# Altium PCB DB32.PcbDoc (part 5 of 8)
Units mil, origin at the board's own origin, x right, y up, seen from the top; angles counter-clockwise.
Board outline 3236.22 x 4456.69 mil, 8 copper layers (Top Layer, MidLayer1, MidLayer2, GND-Layer5, MidLayer3, VCC, MidLayer4, Bottom Layer), stack 61.8 mil thick; 207 components, 474 nets, 1777 pads, 1474 vias.
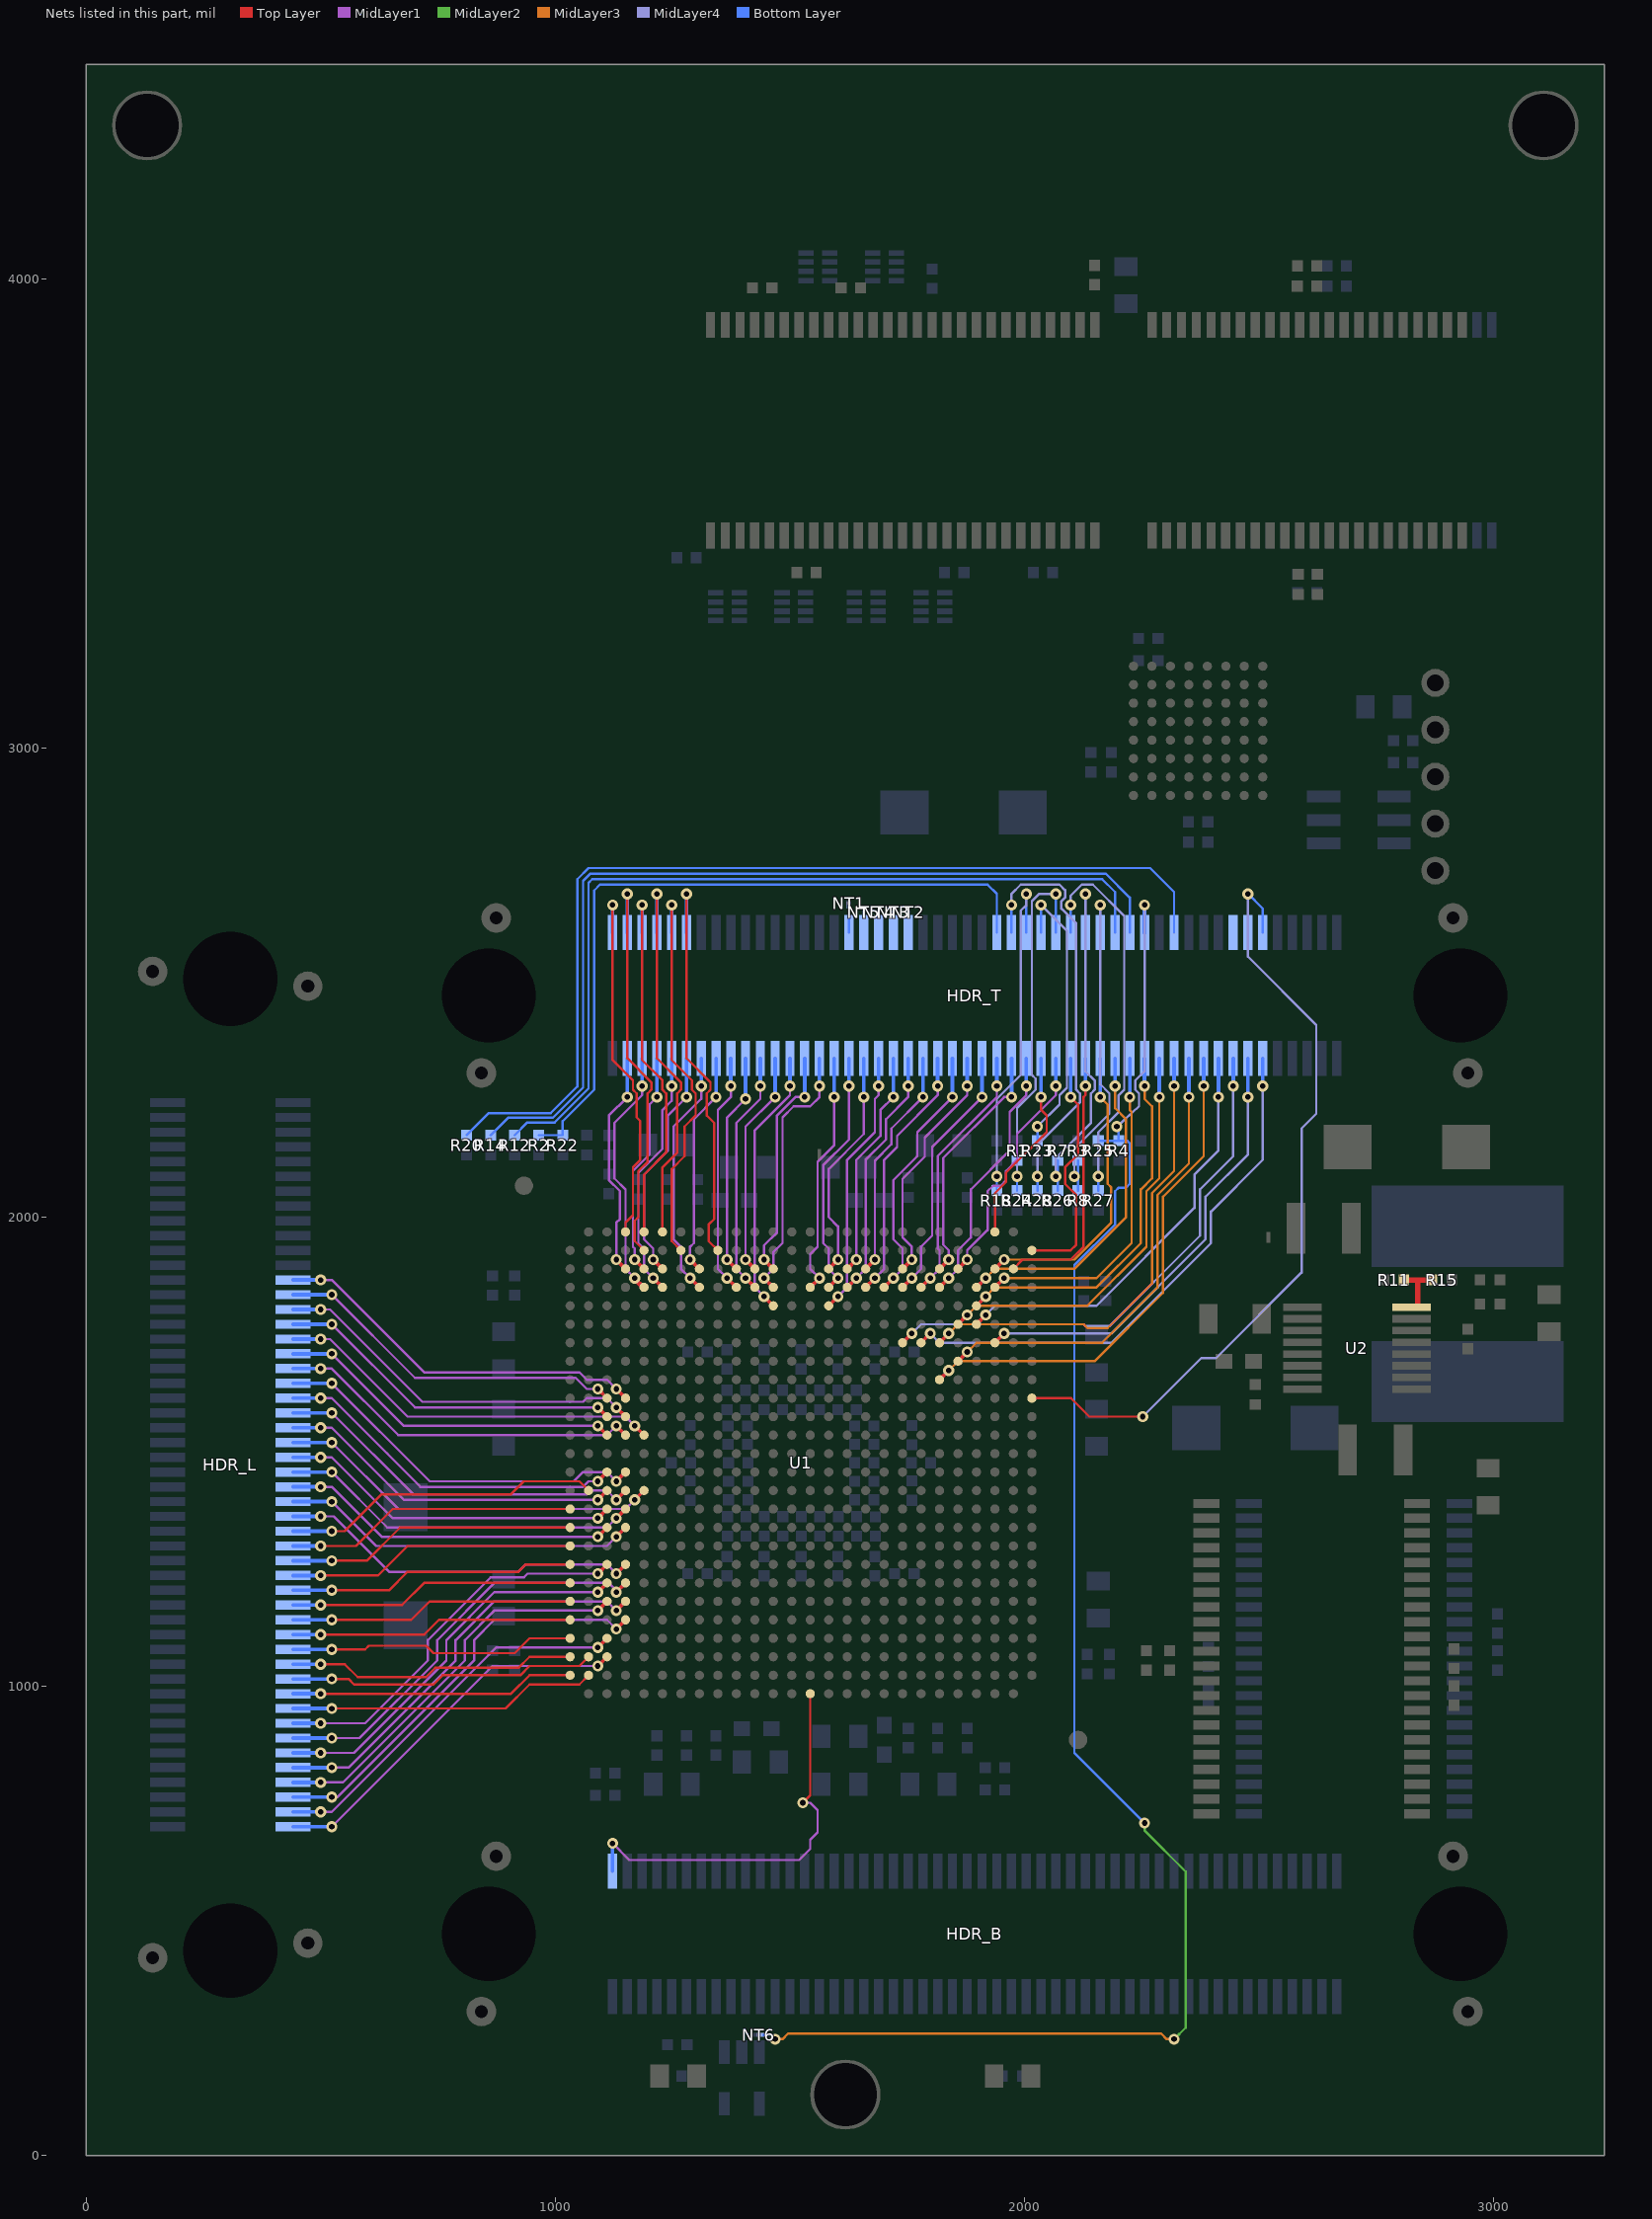
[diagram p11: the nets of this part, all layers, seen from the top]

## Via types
v1: diameter 23.62, hole 11.81, Top Layer to Bottom Layer, 839 vias
v2: diameter 23.62, hole 11.81, Top Layer to Bottom Layer, tented both sides, 499 vias
v3: diameter 27.56, hole 15.75, Top Layer to Bottom Layer, 135 vias
v4: diameter 23.62, hole 11.81, Top Layer to Bottom Layer, tented top, 1 vias

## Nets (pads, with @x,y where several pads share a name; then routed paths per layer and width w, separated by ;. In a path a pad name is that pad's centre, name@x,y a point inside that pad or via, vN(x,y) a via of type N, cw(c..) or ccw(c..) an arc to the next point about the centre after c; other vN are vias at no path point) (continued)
EXTEND_B12: HDR_L.26 U1.K4 | length 813
  Top Layer w7.87: v1(1129.92,1633.86) U1.K4@1149.61,1614.17
  MidLayer1 w5: v2(500,1866.14) 523.62,1866.14 720.47,1669.29 956.69,1669.29 968.5,1669.29 1051.18,1669.29 1066.93,1653.54 1110.23,1653.54 v1(1129.92,1633.86)
  Bottom Layer w7.87: HDR_L.26@440.94,1866.14 v2(500,1866.14)
EXTEND_B13: HDR_L.28 U1.K3 | length 760.6
  Top Layer w7.87: v1(1090.55,1633.86) U1.K3@1110.24,1614.17
  MidLayer1 w5: v2(523.62,1834.65) 700.79,1657.48 956.69,1657.48 968.5,1657.48 1043.31,1657.48 1066.93,1633.86 v1(1090.55,1633.86)
  Bottom Layer w7.87: HDR_L.28@440.94,1834.64 v2(523.62,1834.65)
EXTEND_B14: HDR_L.30 U1.L4 | length 809.8
  Top Layer w7.87: v1(1129.92,1594.49) U1.L4@1149.61,1574.8
  MidLayer1 w5: v2(500,1803.15) 519.68,1803.15 716.54,1606.3 956.69,1606.3 968.5,1606.3 1059.06,1606.3 1066.93,1614.17 1110.23,1614.17 v1(1129.92,1594.49)
  Bottom Layer w7.87: HDR_L.30@440.94,1803.15 v2(500,1803.15)
EXTEND_B15: HDR_L.32 U1.L3 | length 750.8
  Top Layer w7.87: v1(1090.55,1594.49) U1.L3@1110.24,1574.8
  MidLayer1 w5: v2(523.62,1771.66) 700.79,1594.49 956.69,1594.49 968.5,1594.49 v1(1090.55,1594.49)
  Bottom Layer w7.87: HDR_L.32@440.94,1771.65 v2(523.62,1771.66)
EXTEND_B16: HDR_L.34 U1.M5 | length 832.8
  Top Layer w7.87: v1(1169.29,1555.12) U1.M5@1188.98,1535.43
  MidLayer1 w5: v2(500,1740.16) 519.68,1740.16 685.04,1574.8 956.69,1574.8 968.5,1574.8 1149.61,1574.8 v1(1169.29,1555.12)
  Bottom Layer w7.87: HDR_L.34@440.94,1740.15 v2(500,1740.16)
EXTEND_B17: HDR_L.36 U1.M3 | length 741
  Top Layer w7.87: v1(1090.55,1555.12) U1.M3@1110.24,1535.43
  MidLayer1 w5: v2(523.62,1708.66) 677.17,1555.12 956.69,1555.12 968.51,1555.12 v1@1090.55,1555.12
  Bottom Layer w7.87: HDR_L.36@440.94,1708.66 v2(523.62,1708.66)
EXTEND_B18: HDR_L.38 U1.M4 | length 783.7
  Top Layer w7.87: v1(1129.92,1555.12) U1.M4@1149.61,1535.43
  MidLayer1 w5: v2(500,1677.17) 523.62,1677.17 665.36,1535.43 956.69,1535.43 968.5,1535.43 1110.23,1535.43 v1(1129.92,1555.12)
  Bottom Layer w7.87: HDR_L.38@440.94,1677.16 v2(500,1677.17)
EXTEND_B19: HDR_L.40 U1.P4 | length 819.6
  Top Layer w7.87: v1(1129.92,1437.01) U1.P4@1149.61,1456.69
  MidLayer1 w5: v2(523.62,1645.67) 732.29,1437.01 956.69,1437.01 968.5,1437.01 1039.37,1437.01 1059.06,1456.69 1110.23,1456.69 v1(1129.92,1437.01)
  Bottom Layer w7.87: HDR_L.40@440.94,1645.67 v2(523.62,1645.67)
EXTEND_B20: HDR_L.42 U1.P3 | length 760.6
  Top Layer w7.87: v1(1090.55,1437.01) U1.P3@1110.24,1456.69
  MidLayer1 w5: v2(500,1614.17) 523.62,1614.17 641.73,1496.06 712.6,1425.2 956.69,1425.2 968.5,1425.2 1059.06,1425.2 1070.87,1437.01 v1(1090.55,1437.01)
  Bottom Layer w7.87: HDR_L.42@440.94,1614.17 v2(500,1614.17)
EXTEND_B21: HDR_L.44 U1.R4 | length 800
  Top Layer w7.87: v1(1129.92,1397.64) U1.R4@1149.61,1417.32
  MidLayer1 w5: v2(523.62,1582.68) 696.85,1409.45 956.69,1409.45 968.5,1409.45 1066.93,1409.45 1074.8,1417.32 1110.23,1417.32 v1(1129.92,1397.64)
  Bottom Layer w7.87: HDR_L.44@440.94,1582.67 v2(523.62,1582.68)
EXTEND_B22: HDR_L.46 U1.R3 | length 741
  Top Layer w7.87: v1(1090.55,1397.64) U1.R3@1110.24,1417.32
  MidLayer1 w5: v2(500,1551.18) 523.62,1551.18 677.17,1397.64 956.69,1397.64 968.5,1397.64 v1(1090.55,1397.64)
  Bottom Layer w7.87: HDR_L.46@440.94,1551.18 v2(500,1551.18)
EXTEND_B23: HDR_L.48 U1.R5 | length 823
  Top Layer w7.87: v1(1169.29,1397.64) U1.R5@1188.98,1417.32
  MidLayer1 w5: v2(523.62,1519.68) 665.36,1377.95 956.69,1377.95 968.5,1377.95 1149.61,1377.95 v1(1169.29,1397.64)
  Bottom Layer w7.87: HDR_L.48@440.94,1519.68 v2(523.62,1519.68)
EXTEND_B24: HDR_L.50 U1.T3 | length 731.3
  Top Layer w7.87: v1(1090.55,1358.27) U1.T3@1110.24,1377.95
  MidLayer1 w5: v2(500,1488.19) 523.62,1488.19 653.54,1358.27 956.69,1358.27 968.5,1358.27 1062.99,1358.27 v1(1090.55,1358.27)
  Bottom Layer w7.87: HDR_L.50@440.94,1488.19 v2(500,1488.19)
EXTEND_B25: HDR_L.52 U1.T4 | length 773.9
  Top Layer w7.87: v1(1129.92,1358.27) U1.T4@1149.61,1377.95
  MidLayer1 w5: v2(523.62,1456.69) 641.73,1338.58 956.69,1338.58 968.5,1338.58 1110.24,1338.58 v1(1129.92,1358.27)
  Bottom Layer w7.87: HDR_L.52@440.94,1456.69 v2(523.62,1456.69)
EXTEND_B26: HDR_L.54 U1.U3 | length 721.5
  Top Layer w7.87: v1(1090.55,1318.9) U1.U3@1110.24,1338.58
  MidLayer1 w5: v2(500,1425.2) 523.62,1425.2 629.92,1318.9 956.69,1318.9 968.5,1318.9 v1(1090.55,1318.9)
  Bottom Layer w7.87: HDR_L.54@440.94,1425.19 v2(500,1425.2)
EXTEND_B27: HDR_L.56 U1.U4 | length 764.1
  Top Layer w7.87: v1(1129.92,1318.9) U1.U4@1149.61,1338.58
  MidLayer1 w5: v2(523.62,1393.7) 618.11,1299.21 956.69,1299.21 968.5,1299.21 1110.24,1299.21 v1(1129.92,1318.9)
  Bottom Layer w7.87: HDR_L.56@440.94,1393.7 v2(523.62,1393.7)
EXTEND_B28: HDR_L.58 U1.W4 | length 780.4
  Top Layer w7.87: v1(1129.92,1240.16) U1.W4@1149.61,1259.84
  MidLayer1 w5: v2(500,1362.21) 527.56,1362.21 645.67,1244.09 921.26,1244.09 937.01,1259.84 956.69,1259.84 968.5,1259.84 1110.23,1259.84 v1(1129.92,1240.16)
  Bottom Layer w7.87: HDR_L.58@440.94,1362.2 v2(500,1362.21)
EXTEND_B29: HDR_L.60 U1.R2 | length 682.1
  Top Layer w5: v2(523.62,1330.71) 551.18,1330.71 629.92,1409.45 905.51,1409.45 933.07,1437.01 956.69,1437.01 968.5,1437.01 1051.18,1437.01 U1.R2@1070.87,1417.32
  Bottom Layer w7.87: HDR_L.60@440.94,1330.71 v2(523.62,1330.71)
EXTEND_B30: HDR_L.62 U1.T1 | length 623.2
  Top Layer w5: v2(500,1299.21) 574.8,1299.21 653.54,1377.95 956.69,1377.95 968.5,1377.95 U1.T1@1031.5,1377.95
  Bottom Layer w7.87: HDR_L.62@440.94,1299.21 v2(500,1299.21)
EXTEND_B31: HDR_L.64 U1.U1 | length 619.9
  Top Layer w5: v2(523.62,1267.72) 598.43,1267.72 669.29,1338.58 956.69,1338.58 968.5,1338.58 U1.U1@1031.5,1338.58
  Bottom Layer w7.87: HDR_L.64@440.94,1267.71 v2(523.62,1267.72)
EXTEND_B32: HDR_L.66 U1.V1 | length 616.6
  Top Layer w5: v2(500,1236.22) 622.05,1236.22 685.04,1299.21 956.69,1299.21 968.5,1299.21 U1.V1@1031.5,1299.21
  Bottom Layer w7.87: HDR_L.66@440.94,1236.22 v2(500,1236.22)
EXTEND_B33: HDR_L.68 U1.W1 | length 613.4
  Top Layer w5: v2(523.62,1204.72) 645.67,1204.72 685.04,1244.09 921.26,1244.09 937.01,1259.84 956.69,1259.84 968.5,1259.84 U1.W1@1031.5,1259.84
  Bottom Layer w7.87: HDR_L.68@440.94,1204.72 v2(523.62,1204.72)
EXTEND_B34: HDR_L.70 U1.Y1 | length 610.1
  Top Layer w5: v2(500,1173.23) 673.23,1173.23 720.47,1220.47 956.69,1220.47 968.5,1220.47 U1.Y1@1031.5,1220.47
  Bottom Layer w7.87: HDR_L.70@440.94,1173.23 v2(500,1173.23)
EXTEND_B35: HDR_L.72 U1.AA1 | length 606.9
  Top Layer w5: v2(523.62,1141.73) 692.91,1141.73 732.28,1181.1 956.69,1181.1 968.5,1181.1 U1.AA1@1031.5,1181.1
  Bottom Layer w7.87: HDR_L.72@440.94,1141.73 v2(523.62,1141.73)
EXTEND_B36: HDR_L.74 U1.AB1 | length 603.6
  Top Layer w5: v2(500,1110.24) 720.47,1110.24 751.97,1141.73 956.69,1141.73 968.5,1141.73 U1.AB1@1031.5,1141.73
  Bottom Layer w7.87: HDR_L.74@440.94,1110.23 v2(500,1110.24)
EXTEND_B37: HDR_L.76 U1.AC1 | length 613.4
  Top Layer w5: v2(523.62,1078.74) 594.49,1078.74 602.36,1086.61 724.41,1086.61 740.16,1070.87 913.39,1070.87 944.88,1102.36 956.69,1102.36 968.5,1102.36 U1.AC1@1031.5,1102.36
  Bottom Layer w7.87: HDR_L.76@440.94,1078.74 v2(523.62,1078.74)
EXTEND_B38: HDR_L.78 U1.AD1 | length 619.9
  Top Layer w5: v2(500,1047.25) 551.18,1047.25 578.74,1019.68 724.41,1019.68 744.09,1039.37 921.26,1039.37 944.88,1062.99 956.69,1062.99 968.5,1062.99 U1.AD1@1031.5,1062.99
  Bottom Layer w7.87: HDR_L.78@440.94,1047.24 v2(500,1047.25)
EXTEND_B39: HDR_L.80 U1.AD2 | length 659.3
  Top Layer w5: v2(523.62,1015.75) 559.05,1015.75 570.87,1003.94 740.16,1003.94 759.84,1023.62 925.2,1023.62 944.88,1043.31 956.69,1043.31 968.5,1043.31 1051.18,1043.31 U1.AD2@1070.87,1062.99
  Bottom Layer w7.87: HDR_L.80@440.94,1015.74 v2(523.62,1015.75)
EXTEND_B40: HDR_L.82 U1.AE1 | length 606.9
  Top Layer w5: v2(500,984.25) 905.51,984.25 944.88,1023.62 956.69,1023.62 968.5,1023.62 U1.AE1@1031.5,1023.62
  Bottom Layer w7.87: HDR_L.82@440.94,984.25 v2(500,984.25)
EXTEND_B41: HDR_L.84 U1.AE2 | length 659.3
  Top Layer w5: v2(523.62,952.75) 893.7,952.75 944.88,1003.94 956.69,1003.94 968.5,1003.94 1051.18,1003.94 U1.AE2@1070.87,1023.62
  Bottom Layer w7.87: HDR_L.84@440.94,952.75 v2(523.62,952.75)
EXTEND_B42: HDR_L.86 U1.W3 | length 834.9
  Top Layer w7.87: v1(1090.55,1240.16) U1.W3@1110.24,1259.84
  MidLayer1 w5: v2(500,921.26) 594.49,921.26 728.35,1055.12 728.35,1098.43 862.2,1232.28 933.07,1232.28 940.94,1240.16 956.69,1240.16 968.5,1240.16 v1(1090.55,1240.16)
  Bottom Layer w7.87: HDR_L.86@440.94,921.26 v2(500,921.26)
EXTEND_B43: HDR_L.88 U1.Y4 | length 891.3
  Top Layer w7.87: v1(1129.92,1200.79) U1.Y4@1149.61,1220.47
  MidLayer1 w5: v2(523.62,889.76) 582.68,889.76 748.03,1055.12 748.03,1098.43 870.08,1220.47 956.69,1220.47 968.5,1220.47 1114.17,1220.47 1131.89,1202.76 v1@1133.86,1200.79
  Bottom Layer w7.87: HDR_L.88@440.94,889.76 v2(523.62,889.76)
EXTEND_B44: HDR_L.90 U1.Y3 | length 844.7
  Top Layer w7.87: v1(1090.55,1200.79) U1.Y3@1110.24,1220.47
  MidLayer1 w5: v2(500,858.27) 570.87,858.27 767.72,1055.12 767.72,1098.43 870.08,1200.79 956.69,1200.79 968.5,1200.79 v1(1090.55,1200.79)
  Bottom Layer w7.87: HDR_L.90@440.94,858.26 v2(500,858.27)
EXTEND_B45: HDR_L.92 U1.AA4 | length 924.9
  Top Layer w7.87: v1(1129.92,1161.42) U1.AA4@1149.61,1181.1 v1(1129.92,1161.42)
  MidLayer1 w5: v2(523.62,826.77) 559.05,826.77 787.4,1055.12 787.4,1098.43 870.08,1181.1 956.69,1181.1 968.5,1181.1 1110.23,1181.1 v1(1129.92,1161.42)
  Bottom Layer w7.87: HDR_L.92@440.94,826.77 v2(523.62,826.77)
EXTEND_B46: HDR_L.94 U1.AA3 | length 902
  Top Layer w7.87: v1(1090.55,1161.42) U1.AA3@1110.24,1181.1 v1(1090.55,1161.42)
  MidLayer1 w5: v2(500,795.28) 547.24,795.28 807.09,1055.12 807.09,1098.43 870.08,1161.42 956.69,1161.42 968.5,1161.42 v1(1090.55,1161.42) 1070.87,1161.41
  Bottom Layer w7.87: HDR_L.94@440.94,795.27 v2(500,795.28)
EXTEND_B47: HDR_L.96 U1.AB4 | length 974.1
  Top Layer w7.87: v1(1129.92,1122.05) U1.AB4@1149.61,1141.73 v1(1129.92,1122.05)
  MidLayer1 w5: v2(523.62,763.78) 535.43,763.78 826.77,1055.12 826.77,1098.43 870.08,1141.73 956.69,1141.73 968.5,1141.73 1110.23,1141.73 ; 1070.87,1141.73 1110.24,1141.73 ; v1(1129.92,1122.05) 1110.23,1141.73
  Bottom Layer w7.87: HDR_L.96@440.95,763.78 v2(523.62,763.78)
EXTEND_B48: HDR_L.98 U1.AC3 | length 822.6
  Top Layer w7.87: v1(1090.55,1082.68) U1.AC3@1110.24,1102.36
  MidLayer1 w5: v2(500,732.28) 523.62,732.28 874.02,1082.68 956.69,1082.68 968.5,1082.68 v1(1090.55,1082.68)
  Bottom Layer w7.87: HDR_L.98@440.94,732.28 v2(500,732.28)
EXTEND_B49: HDR_L.100 U1.AD3 | length 819.3
  Top Layer w7.87: v1(1090.55,1043.31) U1.AD3@1110.24,1062.99
  MidLayer1 w5: v2(523.62,700.79) 866.14,1043.31 956.69,1043.31 968.5,1043.3 v1(1090.55,1043.31)
  Bottom Layer w7.87: HDR_L.100@440.94,700.78 v2(523.62,700.79)
EXTEND_C0: HDR_T.89 U1.G20 | length 1220.9
  Top Layer w7.87: U1.G20@1779.53,1732.28 v1(1799.21,1751.97)
  MidLayer4 w5: v1(1799.21,1751.97) 1818.9,1732.28 2078.74,1732.28 2090.55,1732.28 2185.04,1732.28 2397.64,1944.88 2397.64,2011.81 2507.87,2122.05 v2(2507.87,2279.53)
  Bottom Layer w7.87: v2(2507.87,2279.53) HDR_T.89@2507.88,2338.58 v2(2507.87,2279.53)
EXTEND_C1: HDR_T.87 U1.G24 | length 963.5
  Top Layer w7.87: U1.G24@1937.01,1732.28 v1(1956.69,1751.97)
  MidLayer4 w5: v1(1956.69,1751.97) 2078.74,1751.97 2090.55,1751.97 2185.04,1751.97 2385.83,1952.76 2385.83,2043.31 2476.38,2133.86 v2(2476.38,2255.9)
  Bottom Layer w7.87: v2(2476.38,2255.9) HDR_T.87@2476.38,2338.58
EXTEND_C2: HDR_T.85 U1.G19 | length 1139
  Top Layer w7.87: U1.G19@1740.16,1732.28 v1(1759.84,1751.97)
  MidLayer4 w5: v1(1759.84,1751.97) 1779.53,1771.65 2078.74,1771.65 2090.55,1771.65 2125.98,1771.65 2129.92,1767.72 2181.1,1767.72 2374.02,1960.63 2374.02,2059.06 2444.88,2129.92 v2(2444.88,2279.53)
  Bottom Layer w7.87: v2(2444.88,2279.53) HDR_T.85@2444.88,2338.58
EXTEND_C3: HDR_T.83 U1.F23 | length 907.4
  Top Layer w7.87: U1.F23@1897.64,1771.65 v1(1917.33,1791.34)
  MidLayer4 w5: v1(1917.33,1791.34) 1937.01,1811.02 2078.74,1811.02 2090.55,1811.02 2153.54,1811.02 2362.2,2019.68 2362.2,2090.55 2413.38,2141.73 v2(2413.38,2255.9)
  Bottom Layer w7.87: v2(2413.38,2255.9) HDR_T.83@2413.39,2338.58
EXTEND_C4: HDR_T.81 U1.J21 | length 1088.9
  Top Layer w7.87: U1.J21@1818.9,1653.54 v1(1838.59,1673.23)
  MidLayer3 w5: v1(1838.59,1673.23) 1858.27,1692.91 2078.74,1692.91 2090.55,1692.91 2149.61,1692.91 2295.28,1838.58 2295.28,2043.31 2381.89,2129.92 v2(2381.89,2279.53)
  Bottom Layer w7.87: v2(2381.89,2279.53) HDR_T.81@2381.89,2338.58
EXTEND_C5: HDR_T.79 U1.H22 | length 1006.3
  Top Layer w7.87: U1.H22@1858.27,1692.91 v1(1877.96,1712.6)
  MidLayer3 w5: v1(1877.96,1712.6) 1897.64,1732.28 2078.74,1732.28 2090.55,1732.28 2165.35,1732.28 2283.46,1850.39 2283.46,2047.24 2350.39,2114.17 v2(2350.39,2255.9)
  Bottom Layer w7.87: v2(2350.39,2255.9) HDR_T.79@2350.4,2338.58
EXTEND_C6: HDR_T.77 U1.G21 | length 1011.3
  Top Layer w7.87: U1.G21@1818.9,1732.28 v1(1838.58,1751.97)
  MidLayer3 w5: v1(1838.58,1751.97) 1858.27,1771.65 2078.74,1771.65 2090.55,1771.65 2125.98,1771.65 2133.86,1763.78 2177.17,1763.78 2271.65,1858.27 2271.65,2051.18 2318.89,2098.42 v2(2318.89,2279.53)
  Bottom Layer w7.87: v2(2318.89,2279.53) HDR_T.77@2318.9,2338.58
EXTEND_C7: HDR_T.75 U1.F22 | length 883.1
  Top Layer w7.87: U1.F22@1858.27,1771.65 v1(1877.96,1791.34)
  MidLayer3 w5: v1(1877.96,1791.34) 1897.64,1811.02 2078.74,1811.02 2090.55,1811.02 2133.86,1811.02 2259.84,1937.01 2259.84,2055.12 2287.4,2082.68 v2(2287.4,2255.9)
  Bottom Layer w7.87: v2(2287.4,2255.9) HDR_T.75@2287.4,2338.58
EXTEND_C8: HDR_T.73 U1.E23 | length 815.8
  Top Layer w7.87: U1.E23@1897.64,1811.02 v1(1917.32,1830.71)
  MidLayer3 w5: v1(1917.32,1830.71) 1937.01,1850.39 2078.74,1850.39 2090.55,1850.39 2153.54,1850.39 2248.03,1944.88 2248.03,2059.06 2271.65,2082.68 2271.65,2236.21 2255.9,2251.97 v2(2255.9,2279.53)
  Bottom Layer w7.87: v2(2255.9,2279.53) HDR_T.73@2255.91,2338.58
EXTEND_C9: HDR_T.71 U1.D24 | length 725.8
  Top Layer w7.87: U1.D24@1937.01,1850.39 v1(1956.7,1870.08)
  MidLayer3 w5: v1(1956.7,1870.08) 2078.74,1870.08 2090.55,1870.08 2153.54,1870.08 2228.35,1944.88 2228.35,2224.41 2224.41,2228.35 v2(2224.41,2255.9)
  Bottom Layer w7.87: v2(2224.41,2255.9) HDR_T.71@2224.41,2338.58
EXTEND_C10: HDR_T.69 U1.D23 | length 729.2
  Top Layer w7.87: U1.D23@1897.64,1850.39 v1(1917.33,1870.08)
  MidLayer3 w5: v1(1917.33,1870.08) 1937.01,1889.76 2078.74,1889.76 2090.55,1889.76 2106.3,1889.76 2216.54,2000 2216.54,2208.66 2192.91,2232.29 v2(2192.91,2279.53)
  Bottom Layer w7.87: v2(2192.91,2279.53) HDR_T.69@2192.91,2338.58
EXTEND_C11: HDR_T.67 U1.C24 | length 649
  Top Layer w7.87: U1.C24@1937.01,1889.76 v1(1956.69,1909.45)
  MidLayer3 w5: v1(1956.69,1909.45) 2078.74,1909.45 2090.55,1909.45 2106.3,1909.45 2185.04,1988.19 2185.04,2062.99 2177.16,2070.87 2177.16,2240.16 v2(2161.42,2255.9)
  Bottom Layer w7.87: v2(2161.42,2255.9) HDR_T.67@2161.42,2338.58
EXTEND_C12: HDR_T.65 U1.C25 | length 572.4
  Top Layer w5: U1.C25@1976.38,1889.76 1996.06,1909.45 2078.74,1909.45 2090.55,1909.45 2098.43,1909.45 2125.98,1937.01 2125.98,2255.91 2129.92,2259.84 v2(2129.92,2279.53)
  Bottom Layer w7.87: v2(2129.92,2279.53) HDR_T.65@2129.92,2338.58
EXTEND_C13: HDR_T.63 U1.B26 | length 524.7
  Top Layer w5: U1.B26@2015.75,1929.13 2078.74,1929.13 2090.55,1929.13 2098.43,1929.13 2110.24,1940.94 2110.24,2047.24 2086.61,2070.87 2086.61,2106.3 2114.17,2133.86 2114.17,2240.16 v2(2098.42,2255.9)
  Bottom Layer w7.87: v2(2098.42,2255.9) HDR_T.63@2098.43,2338.58
EXTEND_C14: HDR_T.61 U1.C22 | length 544.5
  Top Layer w7.87: U1.C22@1858.27,1889.76 v1(1877.95,1909.45)
  MidLayer1 w5: v1(1877.95,1909.45) 1877.95,1929.13 1921.26,1972.44 1921.26,2031.5 1921.26,2043.31 1921.26,2055.12 1933.07,2066.93 1948.82,2066.93 1960.63,2078.74 1960.63,2098.43 1984.25,2122.05 1984.25,2177.17 2066.93,2259.84 v2(2066.93,2279.53)
  Bottom Layer w7.87: v2(2066.93,2279.53) HDR_T.61@2066.93,2338.58
EXTEND_C15: HDR_T.59 U1.A24 | length 420.6
  Top Layer w5: U1.A24@1937.01,1968.5 1937.01,2031.49 1937.01,2043.31 1937.01,2051.18 1960.63,2074.8 1960.63,2094.49 2047.24,2181.1 2047.24,2216.54 2035.43,2228.35 v2(2035.43,2255.9)
  Bottom Layer w7.87: v2(2035.43,2255.9) HDR_T.59@2035.43,2338.58
EXTEND_C16: HDR_T.57 U1.D21 | length 564.8
  Top Layer w7.87: U1.D21@1818.9,1850.39 v1(1838.59,1870.08)
  MidLayer1 w5: v1(1838.59,1870.08) 1858.27,1889.76 1858.27,1929.13 1885.83,1956.69 1885.83,2031.5 1885.83,2043.31 1885.83,2059.06 1968.5,2141.73 1968.5,2224.41 2003.94,2259.84 v2(2003.93,2279.53)
  Bottom Layer w7.87: v2(2003.93,2279.53) HDR_T.57@2003.94,2338.58
EXTEND_C17: HDR_T.55 U1.C21 | length 531.4
  Top Layer w7.87: U1.C21@1818.9,1889.76 v1(1838.58,1909.45)
  MidLayer1 w5: v1(1838.58,1909.45) 1838.58,1929.13 1826.77,1940.95 1826.77,2031.5 1826.77,2043.31 1826.77,2125.98 1956.69,2255.9 v2(1972.44,2255.9)
  Bottom Layer w7.87: v2(1972.44,2255.9) HDR_T.55@1972.44,2338.58
EXTEND_C18: HDR_T.53 U1.D20 | length 558.3
  Top Layer w7.87: U1.D20@1779.53,1850.39 v1(1799.21,1870.08)
  MidLayer1 w5: v1(1799.21,1870.08) 1818.9,1889.76 1818.9,1929.13 1814.96,1933.07 1814.96,2031.5 1814.96,2043.31 1814.96,2129.92 1940.94,2255.9 v2(1940.94,2279.53)
  Bottom Layer w7.87: v2(1940.94,2279.53) HDR_T.53@1940.95,2338.58
EXTEND_C19: HDR_T.51 U1.D19 | length 558.3
  Top Layer w7.87: U1.D19@1740.16,1850.39 v1(1759.84,1870.08)
  MidLayer1 w5: v1(1759.84,1870.08) 1779.53,1889.76 1779.53,1937.01 1803.15,1960.63 1803.15,2031.5 1803.15,2043.31 1803.15,2149.61 v2(1909.45,2255.9)
  Bottom Layer w7.87: v2(1909.45,2255.9) HDR_T.51@1909.45,2338.58
EXTEND_C20: HDR_T.49 U1.C19 | length 522.2
  Top Layer w7.87: U1.C19@1740.16,1889.76 v1(1759.84,1909.45)
  MidLayer1 w5: v1(1759.84,1909.45) 1759.84,1937.01 1740.16,1956.7 1740.16,2031.5 1740.16,2043.31 1740.16,2081.69 1787.4,2128.94 1787.4,2169.29 1877.95,2259.84 v2(1877.95,2279.53)
  Bottom Layer w7.87: v2(1877.95,2279.53) HDR_T.49@1877.95,2338.58
EXTEND_C21: HDR_T.47 U1.D18 | length 564.8
  Top Layer w7.87: U1.D18@1700.79,1850.39 v1(1720.47,1870.08)
  MidLayer1 w5: v1(1720.47,1870.08) 1740.16,1889.76 1740.16,1933.07 1720.47,1952.76 1720.47,2031.5 1720.47,2043.31 1720.47,2078.74 1771.65,2129.92 1771.65,2181.1 v2(1846.46,2255.9)
  Bottom Layer w7.87: v2(1846.46,2255.9) HDR_T.47@1846.46,2338.58
EXTEND_C22: HDR_T.45 U1.D17 | length 551.8
  Top Layer w7.87: U1.D17@1661.42,1850.39 v1(1681.1,1870.08)
  MidLayer1 w5: v1(1681.1,1870.08) 1700.79,1889.77 1700.79,2031.5 1700.79,2043.31 1700.79,2122.05 1728.35,2149.61 1728.35,2173.23 1814.96,2259.84 v2(1814.96,2279.53)
  Bottom Layer w7.87: v2(1814.96,2279.53) HDR_T.45@1814.96,2338.58
EXTEND_C23: HDR_T.43 U1.C17 | length 499.4
  Top Layer w7.87: U1.C17@1661.42,1889.76 v1(1681.1,1909.45)
  MidLayer1 w5: v1(1681.1,1909.45) 1681.1,2031.5 1681.1,2043.31 1681.1,2120.08 1716.54,2155.51 1716.54,2188.98 v2(1783.46,2255.9)
  Bottom Layer w7.87: v2(1783.46,2255.9) HDR_T.43@1783.47,2338.58
EXTEND_C24: HDR_T.41 U1.D16 | length 542
  Top Layer w7.87: U1.D16@1622.05,1850.39 v1(1641.73,1870.08)
  MidLayer1 w5: v1(1641.73,1870.08) 1661.42,1889.77 1661.42,2031.5 1661.42,2043.31 1661.42,2122.05 1704.72,2165.35 1704.72,2208.66 1751.97,2255.9 v2(1751.97,2279.53)
  Bottom Layer w7.87: v2(1751.97,2279.53) HDR_T.41@1751.97,2338.58
EXTEND_C25: HDR_T.39 U1.C16 | length 489.6
  Top Layer w7.87: U1.C16@1622.05,1889.76 v1(1641.73,1909.45)
  MidLayer1 w5: v1(1641.73,1909.45) 1641.73,2031.5 1641.73,2043.31 1641.73,2122.05 1692.91,2173.23 1692.91,2228.35 v2(1720.47,2255.9)
  Bottom Layer w7.87: v2(1720.47,2255.9) HDR_T.39@1720.47,2338.58
EXTEND_C26: HDR_T.37 U1.E15 | length 571.6
  Top Layer w7.87: U1.E15@1582.68,1811.02 v1(1602.36,1830.71)
  MidLayer1 w5: v1(1602.36,1830.71) 1622.05,1850.39 1622.05,2031.5 1622.05,2043.31 1622.05,2122.05 1681.1,2181.1 1681.1,2251.97 1688.98,2259.84 v2(1688.97,2279.53)
  Bottom Layer w7.87: v2(1688.97,2279.53) HDR_T.37@1688.98,2338.58
EXTEND_C27: HDR_T.35 U1.C15 | length 496.1
  Top Layer w7.87: U1.C15@1582.68,1889.76 v1(1602.36,1909.45)
  MidLayer1 w5: v1(1602.36,1909.45) 1602.36,1980.32 1582.68,2000 1582.68,2031.5 1582.68,2043.31 1582.68,2102.36 1657.48,2177.16 v2(1657.48,2255.9)
  Bottom Layer w7.87: v2(1657.48,2255.9) HDR_T.35@1657.48,2338.58
EXTEND_C28: HDR_T.33 U1.D15 | length 532.2
  Top Layer w7.87: U1.D15@1582.68,1850.39 v1(1602.36,1870.08)
  MidLayer1 w5: v1(1602.36,1870.08) 1582.68,1889.77 1582.68,1933.07 1570.87,1944.88 1570.87,2031.5 1570.87,2043.31 1570.87,2110.24 1625.98,2165.35 v2(1625.98,2279.53)
  Bottom Layer w7.87: v2(1625.98,2279.53) HDR_T.33@1625.99,2338.58
EXTEND_C29: HDR_T.31 U1.D14 | length 525.7
  Top Layer w7.87: U1.D14@1543.31,1850.39 v1(1562.99,1870.08)
  MidLayer1 w5: v1(1562.99,1870.08) 1543.31,1889.77 1543.31,1921.26 1559.06,1937.01 1559.06,2031.5 1559.06,2043.31 1559.06,2118.11 1562.99,2122.05 1594.49,2153.54 v2(1594.49,2255.9)
  Bottom Layer w7.87: v2(1594.49,2255.9) HDR_T.31@1594.49,2338.58
EXTEND_C30: HDR_T.29 U1.D12 | length 566
  Top Layer w7.87: v1(1444.88,1870.08) U1.D12@1464.57,1850.39
  MidLayer1 w5: v1(1444.88,1870.08) 1464.57,1889.77 1464.57,1925.2 1484.25,1944.88 1484.25,2031.5 1484.25,2043.31 1484.25,2212.6 1507.87,2236.22 1543.31,2236.22 1562.99,2255.9 v2(1562.99,2279.53)
  Bottom Layer w7.87: v2(1562.99,2279.53) HDR_T.29@1562.99,2338.58
EXTEND_C31: HDR_T.27 U1.C12 | length 504.4
  Top Layer w7.87: v1(1444.88,1909.45) U1.C12@1464.57,1889.76
  MidLayer1 w5: v1(1444.88,1909.45) 1444.88,1939.96 1472.44,1967.52 1472.44,2031.5 1472.44,2043.31 1472.44,2216.54 1511.81,2255.9 v2(1531.5,2255.9)
  Bottom Layer w7.87: v2(1531.5,2255.9) HDR_T.27@1531.5,2338.58
EXTEND_C32: HDR_T.25 U1.E12 | length 574.9
  Top Layer w7.87: v1(1444.88,1830.71) U1.E12@1464.57,1811.02
  MidLayer1 w5: v1(1444.88,1830.71) 1425.2,1850.39 1425.2,2031.5 1425.2,2043.31 1425.2,2185.04 1500,2259.84 v2(1500,2279.53)
  Bottom Layer w7.87: v2(1500,2279.53) HDR_T.25@1500,2338.58
EXTEND_C33: HDR_T.23 U1.C11 | length 483.1
  Top Layer w7.87: v1(1405.51,1909.45) U1.C11@1425.2,1889.76
  MidLayer1 w5: v1(1405.51,1909.45) 1405.51,2031.5 1405.51,2043.31 1405.51,2192.91 v2(1468.5,2255.9)
  Bottom Layer w7.87: v2(1468.5,2255.9) HDR_T.23@1468.5,2338.58
EXTEND_C34: HDR_T.21 U1.D11 | length 525.7
  Top Layer w7.87: v1(1405.51,1870.08) U1.D11@1425.2,1850.39
  MidLayer1 w5: v1(1405.51,1870.08) 1385.83,1889.76 1385.83,2031.5 1385.83,2043.31 1385.83,2200.79 1437.01,2251.97 v2(1437.01,2279.53)
  Bottom Layer w7.87: v2(1437.01,2279.53) HDR_T.21@1437.01,2338.58
EXTEND_C35: HDR_T.19 U1.C10 | length 469.3
  Top Layer w7.87: v1(1366.14,1909.45) U1.C10@1385.83,1889.76
  MidLayer1 w5: v1(1366.14,1909.45) 1366.14,2031.5 1366.14,2043.31 1366.14,2212.6 v2(1405.51,2251.97)
  Bottom Layer w7.87: v2@1405.51,2255.9 HDR_T.19@1405.51,2338.58
EXTEND_C36: HDR_T.17 U1.D10 | length 515.9
  Top Layer w7.87: v1(1366.14,1870.08) U1.D10@1385.83,1850.39
  MidLayer1 w5: v1(1366.14,1870.08) 1346.46,1889.76 1346.46,2031.5 1346.46,2043.31 1346.46,2228.35 1374.02,2255.91 v2(1374.02,2279.53)
  Bottom Layer w7.87: v2(1374.02,2279.53) HDR_T.17@1374.02,2338.58
EXTEND_C37: HDR_T.15 U1.C8 | length 479.8
  Top Layer w7.87: v1(1287.4,1909.45) U1.C8@1307.09,1889.76
  MidLayer1 w5: v1(1287.4,1909.45) 1287.4,1937.01 1295.28,1944.89 1295.28,2031.5 1295.28,2043.31 1295.28,2208.66 v2(1342.52,2255.9)
  Bottom Layer w7.87: v2(1342.52,2255.9) HDR_T.15@1342.52,2338.58
EXTEND_C38: HDR_T.13 U1.D8 | length 535.5
  Top Layer w7.87: v1(1287.4,1870.08) U1.D8@1307.09,1850.39
  MidLayer1 w5: v1(1287.4,1870.08) 1267.72,1889.76 1267.72,1937.01 1251.97,1952.76 1251.97,2031.5 1251.97,2043.31 1251.97,2192.91 1311.02,2251.97 v2(1311.02,2279.53)
  Bottom Layer w7.87: v2(1311.02,2279.53) HDR_T.13@1311.02,2338.58
EXTEND_C39: HDR_T.11 U1.C6 | length 502.6
  Top Layer w7.87: v1(1208.66,1909.45) U1.C6@1228.35,1889.76
  MidLayer1 w5: v1(1208.66,1909.45) 1208.66,1933.07 1188.98,1952.76 1188.98,2031.5 1188.98,2043.31 1188.98,2090.55 1240.16,2141.73 1240.16,2216.53 v2(1279.53,2255.9)
  Bottom Layer w7.87: v2(1279.53,2255.9) HDR_T.11@1279.53,2338.58
EXTEND_C40: HDR_T.12 U1.B9 | length 886.5
  Top Layer w5: v2(1279.53,2688.98) 1279.53,2338.58 1330.71,2287.4 1330.71,2271.65 1322.83,2263.78 1322.83,2216.54 1338.58,2200.79 1338.58,2043.31 1338.58,2031.5 1338.58,1996.06 1326.77,1984.25 1326.77,1948.82 U1.B9@1346.46,1929.13
  Bottom Layer w7.87: HDR_T.12@1279.53,2606.3 v2(1279.53,2688.98)
EXTEND_C41: HDR_T.9 U1.D6 | length 538.7
  Top Layer w7.87: v1(1208.66,1870.08) U1.D6@1228.35,1850.39
  MidLayer1 w5: v1(1208.66,1870.08) 1188.98,1889.76 1188.98,1933.07 1177.17,1944.88 1177.17,2031.5 1177.17,2043.31 1177.17,2094.49 1228.35,2145.67 1228.35,2228.35 1248.03,2248.03 v2(1248.03,2279.53)
  Bottom Layer w7.87: v2(1248.03,2279.53) HDR_T.9@1248.03,2338.58
EXTEND_C42: HDR_T.10 U1.B7 | length 845.8
  Top Layer w5: v2(1248.03,2665.35) 1248.03,2334.65 1291.34,2291.34 1291.34,2271.65 1299.21,2263.78 1299.21,2216.54 1275.59,2192.91 1275.59,2129.92 1248.03,2102.36 1248.03,2043.31 1248.03,2031.49 1248.03,1948.82 U1.B7@1267.72,1929.13
  Bottom Layer w7.87: HDR_T.10@1248.03,2606.3 v2(1248.03,2665.35)
EXTEND_C43: HDR_T.7 U1.C5 | length 479.8
  Top Layer w7.87: v1(1169.29,1909.45) U1.C5@1188.98,1889.76
  MidLayer1 w5: v1(1169.29,1909.45) 1169.29,1933.07 1165.35,1937.01 1165.35,2031.5 1165.35,2043.31 1165.35,2098.43 1200.79,2133.86 1200.79,2240.16 v2(1216.54,2255.9)
  Bottom Layer w7.87: v2(1216.54,2255.9) HDR_T.7@1216.54,2338.58
EXTEND_C44: HDR_T.8 U1.A6 | length 840.7
  Top Layer w5: v2(1216.54,2688.98) 1216.54,2338.58 1267.72,2287.4 1267.72,2271.65 1259.84,2263.78 1259.84,2137.8 1228.35,2106.3 1228.35,2043.31 1228.35,2031.5 U1.A6@1228.35,1968.5
  Bottom Layer w7.87: HDR_T.8@1216.54,2606.3 v2(1216.54,2688.98)
EXTEND_C45: HDR_T.5 U1.D5 | length 566.6
  Top Layer w7.87: v1@1169.28,1866.15 U1.D5@1188.97,1846.46 ; v1(1169.29,1870.08) U1.D5@1188.98,1850.39
  MidLayer1 w5: v1(1169.29,1870.08) 1149.61,1889.76 1149.61,2031.5 1149.61,2043.31 1149.61,2059.06 1125.98,2082.68 1125.98,2200.79 1185.04,2259.84 v2(1185.04,2279.53)
  Bottom Layer w7.87: v2(1185.04,2279.53) HDR_T.5@1185.04,2338.58
EXTEND_C46: HDR_T.6 U1.A5 | length 855.7
  Top Layer w5: v2(1185.04,2665.35) 1185.04,2334.65 1228.35,2291.34 1228.35,2271.65 1236.22,2263.78 1236.22,2137.8 1188.98,2090.55 1188.98,2043.31 1188.98,2031.5 U1.A5@1188.98,1968.5
  Bottom Layer w7.87: HDR_T.6@1185.04,2606.3 v2(1185.04,2665.35) HDR_T.6@1185.04,2606.3
EXTEND_C47: HDR_T.3 U1.C4 | length 486.3
  Top Layer w7.87: v1(1129.92,1909.45) U1.C4@1149.61,1889.76
  MidLayer1 w5: v1(1129.92,1909.45) 1129.92,1988.19 1137.8,1996.06 1137.8,2031.5 1137.8,2043.31 1137.8,2055.12 1114.17,2078.74 1114.17,2216.53 v2(1153.54,2255.9)
  Bottom Layer w7.87: v2(1153.54,2255.9) HDR_T.3@1153.54,2338.58
EXTEND_C48: HDR_T.4 U1.B5 | length 945.6
  Top Layer w5: v2(1153.54,2688.98) 1153.54,2338.58 1204.72,2287.4 1204.72,2271.65 1196.85,2263.78 1196.85,2118.11 1177.17,2098.43 1177.17,2043.31 1177.17,2031.49 1177.17,2000 1169.29,1992.13 1169.29,1948.82 U1.B5@1188.98,1929.13
  Bottom Layer w7.87: 1153.54,2665.35 HDR_T.4@1153.54,2606.3 v2(1153.54,2688.98)
EXTEND_C49: HDR_T.2 U1.A4 | length 793.4
  Top Layer w5: v2(1122.05,2665.35) 1122.05,2334.65 1165.35,2291.34 1165.35,2271.65 1173.23,2263.78 1173.23,2212.6 1181.1,2204.72 1181.1,2122.05 1165.35,2106.3 1165.35,2043.31 1165.35,2031.5 1165.35,2003.94 1149.61,1988.19 U1.A4@1149.61,1968.5
  Bottom Layer w7.87: HDR_T.2@1122.05,2606.3 v2(1122.05,2665.35)
FB: R11.2 R15.1 U2.8 | length 120.2
  Top Layer w7.87: U2.8@2842.51,1807.09 U2.8@2842.51,1808.25
  Top Layer w11.81: R11.2@2808.58,1866.14 2838.58,1866.14 ; U2.8@2838.58,1807.09 2838.58,1808.25 2838.58,1866.14 ; R15.1@2868.58,1866.14 2838.58,1866.14
FPGA_CCLK: HDR_T.66 R7.1 R26.1 | length 791.4
  MidLayer4 w5: v2(2066.93,2086.61) 2066.93,2125.98 2141.73,2200.79 2141.73,2263.78 2149.61,2271.65 2149.61,2291.34 2129.92,2311.02 v2(2129.92,2688.98)
  Bottom Layer w5: R26.1@2070.86,2056.61 2070.86,2086.61 R7.1@2070.86,2120.55 ; HDR_T.66@2129.92,2606.3 v2(2129.92,2688.98)
FPGA_CLK: HDR_B.2 U1.AF14 | length 870.8
  Top Layer w5: v1(1527.56,751.97) 1543.31,767.72 U1.AF14@1543.31,984.25
  MidLayer1 w5: v2(1122.05,665.35) 1157.48,629.92 1519.69,629.92 1543.31,653.54 1543.31,673.23 1559.06,688.98 1559.06,736.22 1543.31,751.97 v1(1527.56,751.97)
  Bottom Layer w7.87: HDR_B.2@1122.05,606.3 v2(1122.05,665.35)
FPGA_CLK1: HDR_T.90 U1.K26 | length 1694.4
  Top Layer w5: U1.K26@2015.75,1614.17 2099.12,1614.17 2138.5,1574.79 v1(2251.96,1574.79)
  MidLayer4 w5: v1(2251.96,1574.79) 2376.85,1699.68 2408.1,1699.68 ; 2408.22,1699.56 2590.55,1881.89 2590.55,2188.98 2622.05,2220.47 2622.05,2409.45 2476.38,2555.12 v2(2476.38,2688.98)
  Bottom Layer w5: v2(2476.38,2688.98) 2507.87,2657.48 HDR_T.90@2507.88,2606.3
FPGA_DIN: HDR_T.64 R27.1 | length 842.3
  MidLayer4 w5: v2(2098.43,2665.35) 2098.43,2685.04 2122.05,2708.66 2145.67,2708.66 2212.6,2641.73 2212.6,2271.65 2200.79,2259.84 2200.79,2224.41 2157.48,2181.1 v2(2157.48,2086.61)
  Bottom Layer w5: HDR_T.64@2098.43,2606.3 v2(2098.43,2665.35) v2@2098.43,2669.29 ; R27.1@2157.48,2056.61 v2(2157.48,2086.61)
FPGA_DONE: HDR_T.74 NT6.2 R4.1 R25.1 | length 3631.5
  MidLayer2 w5: v1(2255.91,708.66) 2255.91,692.71 2343.44,605.18 2343.44,272.57 v1(2318.9,248.03)
  MidLayer3 w5: v1(1468.5,248.03) 1484.25,248.03 1496.06,259.84 2291.34,259.84 2303.15,248.03 v1(2318.9,248.03)
  MidLayer4 w5: v2(2196.85,2192.91) 2244.09,2236.22 2244.09,2263.78 2236.22,2271.65 2236.22,2291.34 2255.9,2311.02 v2(2255.9,2665.35)
  Bottom Layer w5: NT6.2@1443.71,257.11 1459.43,257.11 v1(1468.5,248.03) ; R25.1@2157.48,2162.91 R4.1@2200.78,2162.91 ; v2(2196.85,2192.91) 2200.78,2192.91 R4.1@2200.78,2162.91 ; v1(2255.91,708.66) 2106.3,858.27 2106.3,1897.64 2192.91,1984.25 2192.91,2055.12 2200.79,2062.99 2216.54,2062.99 2224.41,2070.87 2224.41,2157.48 2218.98,2162.91 R4.1@2200.78,2162.91
  Bottom Layer w7.87: HDR_T.74@2255.91,2606.3 v2(2255.9,2665.35)
FPGA_ID0: HDR_T.42 NT2.1
FPGA_ID1: HDR_T.40 NT3.1
FPGA_ID2: HDR_T.38 NT4.1
FPGA_ID3: HDR_T.36 NT5.1
FPGA_INIT: HDR_T.68 R3.1 R8.1 | length 740.9
  MidLayer4 w5: v2(2106.3,2086.61) 2106.3,2145.67 2181.1,2220.47 2181.1,2263.78 2161.42,2283.46 v2(2161.42,2665.35)
  Bottom Layer w5: R8.1@2114.17,2056.61 2114.17,2086.61 R3.1@2114.17,2120.55 ; HDR_T.68@2161.42,2606.3 v2(2161.42,2665.35)
FPGA_INSTALLED: HDR_T.34 NT1.1 | length 58.6
  Bottom Layer w5: HDR_T.34@1625.99,2606.3 NT1.1@1625.99,2664.87
FPGA_M0: HDR_T.60 R23.1 | length 610.4
  MidLayer4 w5: v2(2027.56,2192.91) 2074.8,2240.16 2074.8,2259.84 2090.55,2275.59 2090.55,2610.24 v2(2035.43,2665.35)
  Bottom Layer w5: R23.1@2027.55,2162.91 v2(2027.56,2192.91) ; HDR_T.60@2035.43,2606.3 v2(2035.43,2665.35)
FPGA_M1: HDR_T.58 R18.1 | length 741.1
  MidLayer4 w5: v2(1940.94,2086.61) 1940.94,2251.97 1992.13,2303.15 1992.13,2653.54 2003.94,2665.35 v2(2003.94,2688.98)
  Bottom Layer w5: R18.1@1940.94,2056.61 v2(1940.94,2086.61) ; HDR_T.58@2003.94,2606.3 v2(2003.94,2688.98)
FPGA_M2: HDR_T.56 R28.1 | length 907.2
  MidLayer4 w5: v2(1972.44,2665.35) 1972.44,2688.98 1992.13,2708.66 2074.8,2708.66 2086.61,2696.85 2086.61,2681.1 2078.74,2673.23 2078.74,2657.48 2110.24,2625.98 2110.24,2271.65 2118.11,2263.78 2118.11,2244.09 2027.56,2153.54 v2(2027.56,2086.61)
  Bottom Layer w5: HDR_T.56@1972.44,2606.3 v2(1972.44,2665.35) ; R28.1@2027.55,2056.61 v2(2027.56,2086.61)
FPGA_PROG_CLK: HDR_T.88
FPGA_PROG_PWR_ON: HDR_T.86
FPGA_PROGRAM: HDR_T.62 R1.1 R24.1 | length 810.5
  MidLayer4 w5: v2(1984.25,2086.61) 1984.25,2232.28 2023.62,2271.65 2023.62,2295.28 2015.75,2303.15 2015.75,2673.23 2031.5,2688.98 v2(2066.93,2688.98)
  Bottom Layer w5: R24.1@1984.25,2056.61 v2(1984.25,2086.61) R1.1@1984.25,2120.55 ; HDR_T.62@2066.93,2606.3 v2(2066.93,2688.98)
FPGA_TCK: HDR_T.72 R14.1 | length 1947
  Bottom Layer w5: R14.1@862.2,2174.72 899.19,2211.71 994.45,2211.71 1059.06,2276.32 1059.06,2716.54 1074.8,2732.28 2173.23,2732.28 2224.41,2681.1 HDR_T.72@2224.41,2606.3
FPGA_TDI: HDR_T.78 R20.1 | length 2110.3
  Bottom Layer w5: R20.1@811.02,2174.72 858.01,2221.71 990.31,2221.71 1047.24,2278.65 1047.24,2720.47 1070.87,2744.09 2267.72,2744.09 2318.9,2692.91 HDR_T.78@2318.9,2606.3
FPGA_TDO: HDR_T.54 R2.1 R22.1 | length 1554.6
  Bottom Layer w5: R2.1@964.56,2174.72 R22.1@1015.75,2174.72 1015.74,2204.72 1082.68,2271.65 1082.68,2696.16 1095.18,2708.66 1921.26,2708.66 1940.95,2688.98 HDR_T.54@1940.95,2606.3
FPGA_TMS: HDR_T.70 R12.1 | length 1860.5
  Bottom Layer w5: R12.1@913.38,2174.72 940.38,2201.71 998.59,2201.71 1070.87,2273.98 1070.87,2712.6 1078.74,2720.47 2165.35,2720.47 2192.91,2692.91 HDR_T.70@2192.91,2606.3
